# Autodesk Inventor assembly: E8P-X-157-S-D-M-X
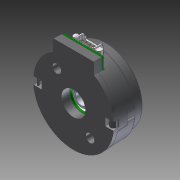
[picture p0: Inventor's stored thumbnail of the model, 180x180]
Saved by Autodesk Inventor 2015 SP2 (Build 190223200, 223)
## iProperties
Created: 2012-07
Part Number: E8P-X-157-S-D-M-X
Document SubType Name: Assembly
Designer: rYan
Mass: 3.85599 g
Surface Area: 74.5599 cm^2
Volume: 3.85599 cm^3
Density: 1 g/cm^3
Author: rYan
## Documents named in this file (8)
- D:\Tigers SVN\mechanik\2016\Inventor\Kaufteile\E8P-X-157-S-D-M-X\E8P-X-157-S-D-M-X.iam
- D:\Tigers SVN\mechanik\2016\Inventor\Kaufteile\E8P-X-157-S-D-M-X\E8P-X-157-S-D-M-X.ipt
- D:\Tigers SVN\mechanik\2016\Inventor\Kaufteile\E8P-X-157-S-D-M-X\E8P-X-157-S-D-M-X_1.ipt
- D:\Tigers SVN\mechanik\2016\Inventor\Kaufteile\E8P-X-157-S-D-M-X\E8P-X-157-S-D-M-X_2.ipt
- D:\Tigers SVN\mechanik\2016\Inventor\Kaufteile\E8P-X-157-S-D-M-X\E8P-X-157-S-D-M-X_3.ipt
- D:\Tigers SVN\mechanik\2016\Inventor\Kaufteile\E8P-X-157-S-D-M-X\E8P-X-157-S-D-M-X_4.ipt
- D:\Tigers SVN\mechanik\2016\Inventor\Kaufteile\E8P-X-157-S-D-M-X\E8P-X-157-S-D-M-X_5.ipt
- D:\Tigers SVN\mechanik\2016\Inventor\Kaufteile\E8P-X-157-S-D-M-X\E8P-X-157-S-D-M-X_6.ipt
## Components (7 placed, 7 different names)
1. E8P-X-157-S-D-M-X:1
2. E8P-X-157-S-D-M-X_1:1
3. E8P-X-157-S-D-M-X_2:1
4. E8P-X-157-S-D-M-X_3:1
5. E8P-X-157-S-D-M-X_4:1
6. E8P-X-157-S-D-M-X_5:1
7. E8P-X-157-S-D-M-X_6:1
